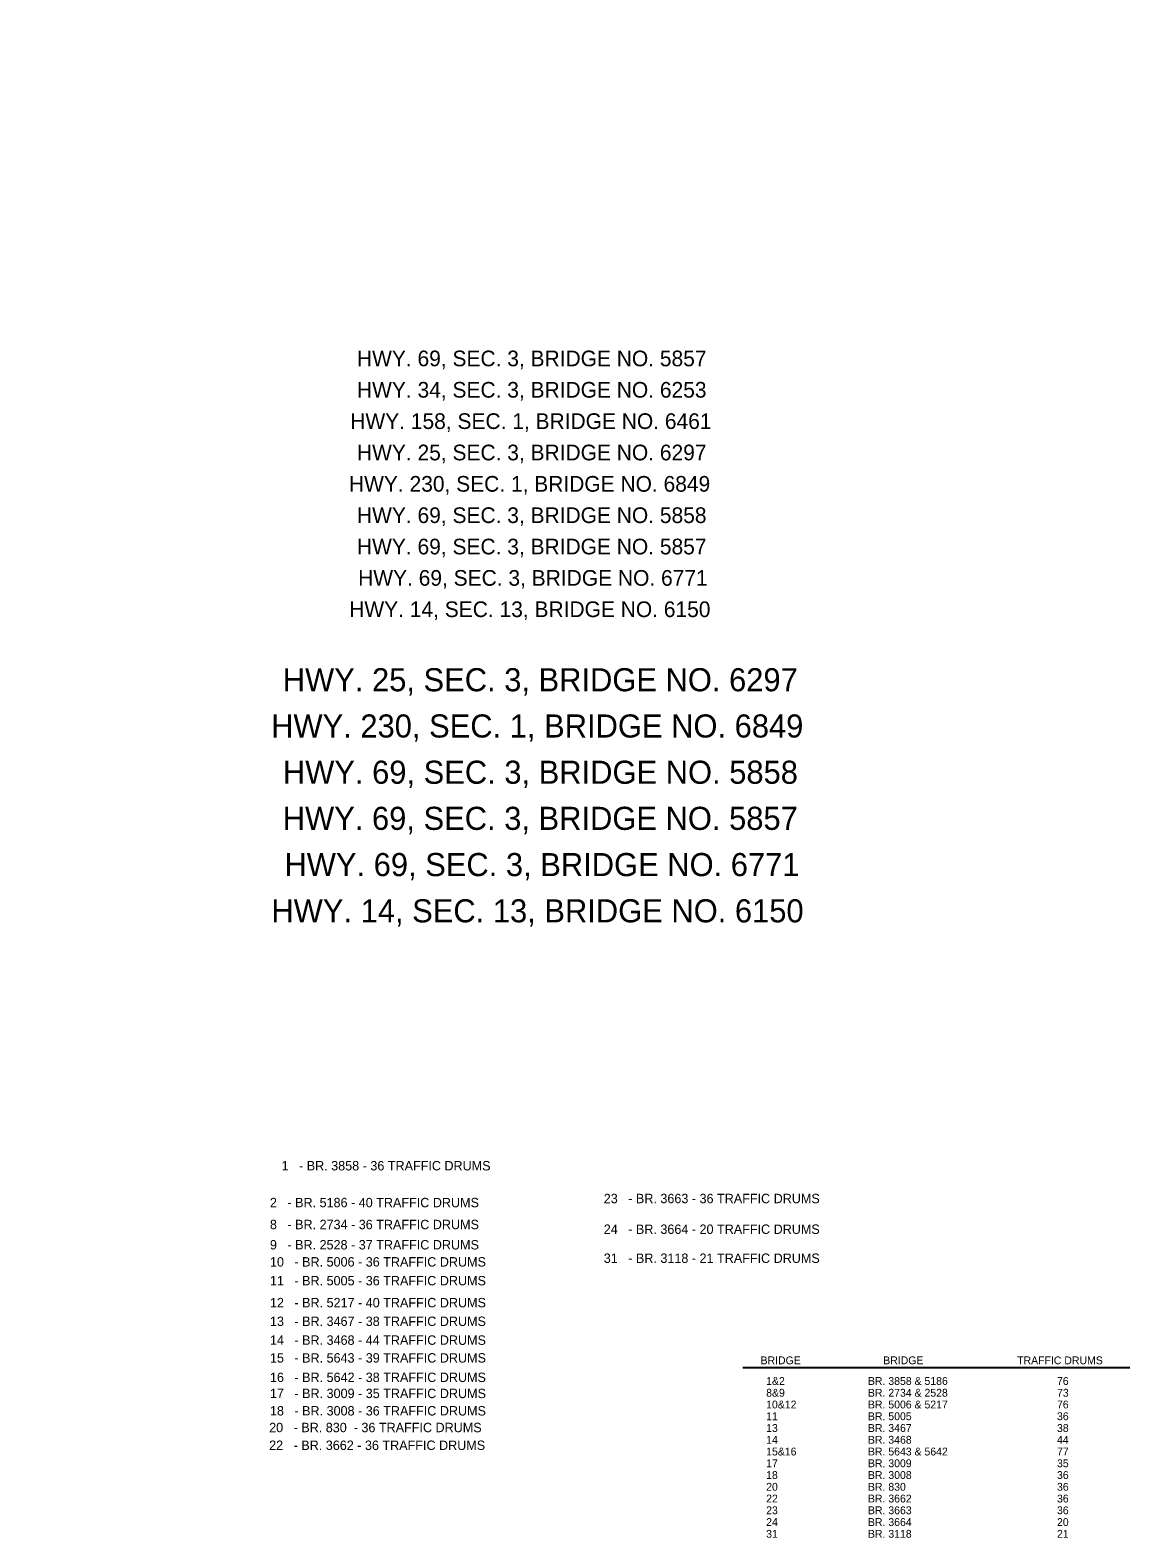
# Model space of a CAD drawing. Extents: x 1930579 to 1934718, y 596452 to 597844.
# Drawn here: x 1933876 to 1934718, y 596501 to 597655 of the extents above; entities that cross this region are included whole.
import ezdxf

# ---------------------------------------------------------------- set-up
doc = ezdxf.new("R2010")
doc.units = 0
for name, color, linetype in [('Default', 7, 'Continuous'), ('R_Annotation', 7, 'Continuous'), ('R_Border', 7, 'Continuous')]:
    doc.layers.add(name, color=color, linetype=linetype)

msp = doc.modelspace()

# ---------------------------------------------------------------- linework, layer by layer
at = {"layer": 'R_Annotation'}
msp.add_line((1934421.8, 596631.1), (1934718, 596631.1), dxfattribs=at)
at = {"layer": 'R_Border'}
msp.add_line((1933876.4, 597654.8), (1933876.4, 597654.8), dxfattribs=at)

# ---------------------------------------------------------------- texts
at = {"layer": 'Default'}
for s, height, p in [('HWY. 69, SEC. 3, BRIDGE NO. 5857', 12, (1934126.5, 597397.5)), ('HWY. 34, SEC. 3, BRIDGE NO. 6253', 12, (1934126.5, 597373.5)), ('HWY. 158, SEC. 1, BRIDGE NO. 6461', 12, (1934121.4, 597349.5)), ('HWY. 25, SEC. 3, BRIDGE NO. 6297', 12, (1934126.5, 597325.5)), ('HWY. 230, SEC. 1, BRIDGE NO. 6849', 12, (1934120.4, 597301.5)), ('HWY. 69, SEC. 3, BRIDGE NO. 5858', 12, (1934126.5, 597277.5)), ('HWY. 69, SEC. 3, BRIDGE NO. 5857', 12, (1934126.5, 597253.5)), ('HWY. 69, SEC. 3, BRIDGE NO. 6771', 12, (1934127.4, 597229.5)), ('HWY. 14, SEC. 13, BRIDGE NO. 6150', 12, (1934120.6, 597205.5)), ('HWY. 25, SEC. 3, BRIDGE NO. 6297', 17.682, (1934069.7, 597148.7)), ('HWY. 230, SEC. 1, BRIDGE NO. 6849', 17.682, (1934060.8, 597113.3)), ('HWY. 69, SEC. 3, BRIDGE NO. 5858', 17.682, (1934069.8, 597077.9)), ('HWY. 69, SEC. 3, BRIDGE NO. 5857', 17.682, (1934069.7, 597042.6)), ('HWY. 69, SEC. 3, BRIDGE NO. 6771', 17.682, (1934071, 597007.2)), ('HWY. 14, SEC. 13, BRIDGE NO. 6150', 17.682, (1934061, 596971.8))]:
    msp.add_text(s, height=height, rotation=360, dxfattribs=at).set_placement(p)
at = {"layer": 'R_Annotation'}
for s, height, p in [('1   - BR. 3858 - 36 TRAFFIC DRUMS', 7.2, (1934068.8, 596781.9)), ('2   - BR. 5186 - 40 TRAFFIC DRUMS', 7.2, (1934059.9, 596753.7)), ('23   - BR. 3663 - 36 TRAFFIC DRUMS', 7.2, (1934315.4, 596756.8)), ('8   - BR. 2734 - 36 TRAFFIC DRUMS', 7.2, (1934059.9, 596736.9)), ('24   - BR. 3664 - 20 TRAFFIC DRUMS', 7.2, (1934315.4, 596733.3)), ('9   - BR. 2528 - 37 TRAFFIC DRUMS', 7.2, (1934059.9, 596721.4)), ('10   - BR. 5006 - 36 TRAFFIC DRUMS', 7.2, (1934059.9, 596708.3)), ('31   - BR. 3118 - 21 TRAFFIC DRUMS', 7.2, (1934315.4, 596711.1)), ('11   - BR. 5005 - 36 TRAFFIC DRUMS', 7.2, (1934059.9, 596693.9)), ('12   - BR. 5217 - 40 TRAFFIC DRUMS', 7.2, (1934059.9, 596677.1)), ('13   - BR. 3467 - 38 TRAFFIC DRUMS', 7.2, (1934059.9, 596662.8)), ('14   - BR. 3468 - 44 TRAFFIC DRUMS', 7.2, (1934059.9, 596648.4)), ('15   - BR. 5643 - 39 TRAFFIC DRUMS', 7.2, (1934059.9, 596634.8)), ('BRIDGE ', 6, (1934435.4, 596633.5)), ('BRIDGE ', 6, (1934529.3, 596633.5)), ('TRAFFIC DRUMS', 6, (1934631.8, 596633.5)), ('16   - BR. 5642 - 38 TRAFFIC DRUMS', 7.2, (1934059.9, 596619.9)), ('1&2', 6, (1934439.7, 596617.7)), ('BR. 3858 & 5186', 6, (1934517.6, 596617.7)), ('76', 6, (1934662.3, 596617.7)), ('17   - BR. 3009 - 35 TRAFFIC DRUMS', 7.2, (1934059.9, 596607.6)), ('8&9', 6, (1934439.7, 596608.7)), ('10&12', 6, (1934439.7, 596599.7)), ('BR. 2734 & 2528', 6, (1934517.6, 596608.7)), ('BR. 5006 & 5217', 6, (1934517.6, 596599.7)), ('73', 6, (1934662.3, 596608.7)), ('76', 6, (1934662.3, 596599.7)), ('18   - BR. 3008 - 36 TRAFFIC DRUMS', 7.2, (1934059.9, 596594.3)), ('11', 6, (1934439.7, 596590.7)), ('BR. 5005', 6, (1934517.6, 596590.7)), ('36', 6, (1934662.3, 596590.7)), ('20   - BR. 830  - 36 TRAFFIC DRUMS', 7.2, (1934059.3, 596581.5)), ('13', 6, (1934439.7, 596581.7)), ('BR. 3467', 6, (1934517.6, 596581.7)), ('38', 6, (1934662.3, 596581.7)), ('22   - BR. 3662 - 36 TRAFFIC DRUMS', 7.2, (1934059.3, 596567.9)), ('14', 6, (1934439.7, 596572.7)), ('15&16', 6, (1934439.7, 596563.7)), ('BR. 3468', 6, (1934517.6, 596572.7)), ('BR. 5643 & 5642', 6, (1934517.6, 596563.7)), ('44', 6, (1934662.3, 596572.7)), ('77', 6, (1934662.3, 596563.7)), ('17', 6, (1934439.7, 596554.7)), ('BR. 3009', 6, (1934517.6, 596554.7)), ('35', 6, (1934662.3, 596554.7)), ('18', 6, (1934439.7, 596545.7)), ('BR. 3008', 6, (1934517.6, 596545.7)), ('36', 6, (1934662.3, 596545.7)), ('20', 6, (1934439.7, 596536.7)), ('BR. 830', 6, (1934517.6, 596536.7)), ('36', 6, (1934662.3, 596536.7)), ('22', 6, (1934439.7, 596527.7)), ('23', 6, (1934439.7, 596518.7)), ('BR. 3662', 6, (1934517.6, 596527.7)), ('BR. 3663', 6, (1934517.6, 596518.7)), ('36', 6, (1934662.3, 596527.7)), ('36', 6, (1934662.3, 596518.7)), ('24', 6, (1934439.7, 596509.7)), ('BR. 3664', 6, (1934517.6, 596509.7)), ('20', 6, (1934662.3, 596509.7)), ('31', 6, (1934439.7, 596500.7)), ('BR. 3118', 6, (1934517.6, 596500.7)), ('21', 6, (1934662.3, 596500.7))]:
    msp.add_text(s, height=height, rotation=360, dxfattribs=at).set_placement(p)

doc.saveas('drawing.dxf')
